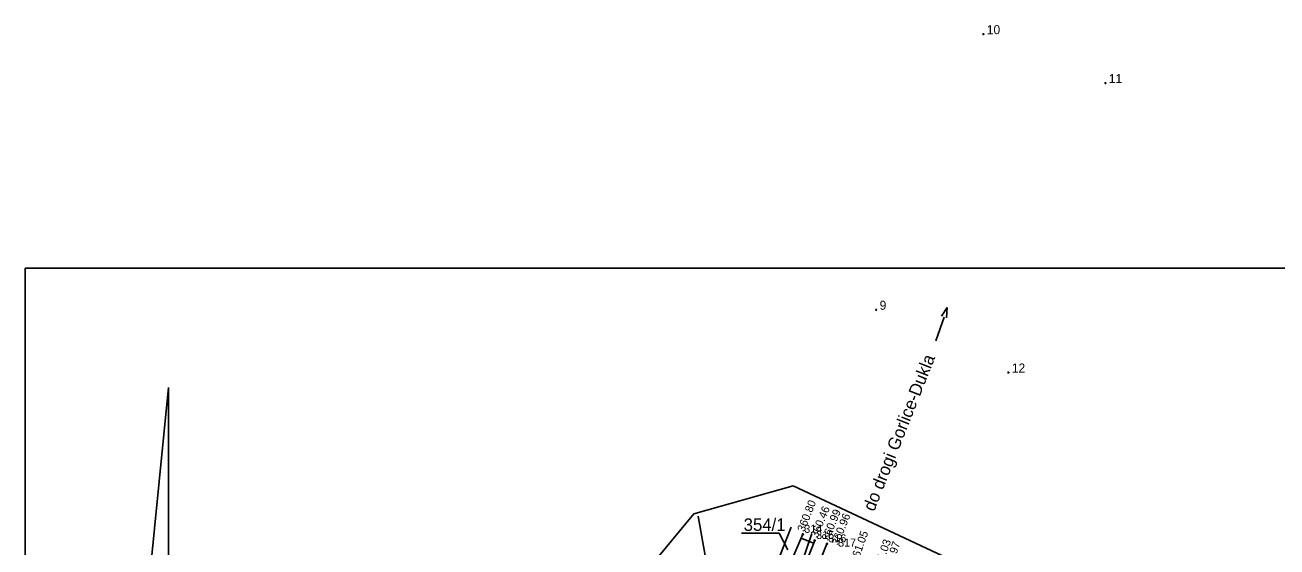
# Model space of a CAD drawing. Extents: x 4635329 to 4651863, y 5356628 to 5367582.
# Drawn here: x 4651671.4 to 4651796.5, y 5357217 to 5357269.1 of the extents above; entities that cross this region are included whole.
import ezdxf

# ---------------------------------------------------------------- set-up
doc = ezdxf.new("R2010")
doc.units = 0
for name, color, linetype in [('Level 1', 7, 'Continuous'), ('Level 13', 7, 'Continuous'), ('Level 21', 7, 'Continuous'), ('Level 4', 7, 'Continuous'), ('Level 44', 7, 'Continuous'), ('Level 45', 7, 'Continuous'), ('Level 48', 7, 'Continuous'), ('Level 5', 7, 'Continuous'), ('Level 62', 7, 'Continuous'), ('Level 63', 7, 'Continuous')]:
    doc.layers.add(name, color=color, linetype=linetype)

msp = doc.modelspace()

# ---------------------------------------------------------------- linework, layer by layer
at = {"layer": 'Level 1'}
for p, q in [((4651748.15, 5357223.09), (4651738.21, 5357220.3)), ((4651784.41, 5357206.11), (4651748.15, 5357223.09)), ((4651738.21, 5357220.3), (4651710.48, 5357186.84))]:
    msp.add_line(p, q, dxfattribs=at)
at = {"layer": 'Level 13'}
for q in [(4651683.78, 5357213.46), (4651685.72, 5357203.86)]:
    msp.add_line((4651685.72, 5357232.92), q, dxfattribs=at)
msp.add_lwpolyline([(4651671.38, 5357244.83), (4651857.01, 5357244.83), (4651857.01, 5357005.82), (4651671.38, 5357005.82)], close=True, dxfattribs=at)
at = {"layer": 'Level 21'}
for p, q in [((4651762.98, 5357240.03), (4651763.54, 5357240.9)), ((4651763.54, 5357240.9), (4651763.46, 5357239.87)), ((4651762.41, 5357237.59), (4651763.22, 5357239.95))]:
    msp.add_line(p, q, dxfattribs=at)
at = {"layer": 'Level 4'}
for p, q in [((4651742.99, 5357218.34), (4651746.74, 5357218.34)), ((4651745.05, 5357211.61), (4651747.94, 5357218.97)), ((4651746.74, 5357218.34), (4651747.62, 5357216.68)), ((4651747.65, 5357211.45), (4651750.01, 5357218.31))]:
    msp.add_line(p, q, dxfattribs=at)
at = {"layer": 'Level 44'}
for centre in [(4651749.11, 5357218.24), (4651750.3, 5357217.62), (4651751.52, 5357217.29)]:
    msp.add_circle(centre, 0.04, dxfattribs=at)
at = {"layer": 'Level 48'}
msp.add_line((4651748.95, 5357217.87), (4651750.19, 5357217.34), dxfattribs=at)
for points in [[(4651713.66, 5357186.38), (4651728.18, 5357201.34), (4651734.81, 5357205.74), (4651738.92, 5357205.32), (4651740.01, 5357212.35), (4651738.64, 5357220.07)], [(4651731.56, 5357173.2), (4651733.61, 5357180.69), (4651738.3, 5357193.27), (4651741.38, 5357200.19), (4651749.11, 5357218.24)], [(4651750.3, 5357217.62), (4651740.18, 5357192.43), (4651735.38, 5357180.1), (4651732.67, 5357172.89)], [(4651751.52, 5357217.29), (4651741.35, 5357191.91), (4651736.4, 5357179.58), (4651733.75, 5357172.51)]]:
    msp.add_lwpolyline(points, dxfattribs=at)
at = {"layer": 'Level 62'}
for centre in [(4651767.16, 5357268.22), (4651779.35, 5357263.33), (4651756.45, 5357240.68), (4651769.66, 5357234.41)]:
    msp.add_circle(centre, 0.05, dxfattribs=at)
at = {"layer": 'Level 63'}
for centre in [(4651749.11, 5357218.24), (4651750.3, 5357217.62), (4651751.52, 5357217.29)]:
    msp.add_circle(centre, 0.06, dxfattribs=at)

# ---------------------------------------------------------------- texts
at = {"layer": 'Level 21'}
msp.add_text('do drogi Gorlice-Dukla', height=1.25, rotation=68.422, dxfattribs=at).set_placement((4651756.24, 5357220.45))
at = {"layer": 'Level 45'}
for s, rotation, p in [('360.80', 68.3808, (4651749.25, 5357218.42)), ('360.46', 67.2991, (4651750.57, 5357217.82)), ('360.99', 67.4884, (4651751.69, 5357217.52)), ('360.96', 68.1344, (4651752.67, 5357217.09)), ('361.05', 70.4198, (4651754.57, 5357215.33)), ('361.03', 70.4275, (4651756.85, 5357214.49)), ('360.97', 71.5715, (4651757.83, 5357214.26))]:
    msp.add_text(s, height=0.8, rotation=rotation, dxfattribs=at).set_placement(p)
at = {"layer": 'Level 5'}
msp.add_text('354/1', height=1.25, dxfattribs=at).set_placement((4651743.2, 5357218.58))
at = {"layer": 'Level 62'}
for s, p in [(' 10', (4651767.16, 5357268.22)), (' 11', (4651779.35, 5357263.33)), (' 9', (4651756.45, 5357240.68)), (' 12', (4651769.66, 5357234.41))]:
    msp.add_text(s, height=0.9, dxfattribs=at).set_placement(p)
at = {"layer": 'Level 63'}
for s, p in [('314', (4651749.26, 5357218.39)), ('315', (4651750.45, 5357217.77)), ('316', (4651751.67, 5357217.44)), ('317', (4651752.64, 5357217.01))]:
    msp.add_text(s, height=0.8, dxfattribs=at).set_placement(p)

doc.saveas('drawing.dxf')
